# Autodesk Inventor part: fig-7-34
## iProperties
Shininess: 77.0
Length Units: 11269
Angle Units: 11279
Time Units: 11290
Mass Units: 11283
Length Display Precision: 3
Angle Display Precision: 2
Created: 2002-01
Part Number: fig-7-34
Document SubType Name: Modeling
Designer: CADSoft
Density: 1 g/cm^3
Density: 0.0
Volumn: 0.0
Area: 0.0
PropertySet Name: Model Information
Control State: 0
Master: False
Checked Out: False
Author: CADSoft
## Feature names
1. Coil5
